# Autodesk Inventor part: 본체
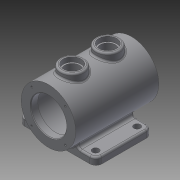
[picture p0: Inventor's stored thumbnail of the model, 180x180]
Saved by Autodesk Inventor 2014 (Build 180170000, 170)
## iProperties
Created: 2014-12
Part Number: 본체
Material: 일반
Document SubType Name: Modeling
Designer: Owner
Density: 1 g/cm^3
Appearance: 기본값
Author: Owner
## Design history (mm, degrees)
sketch "스케치1"
  geometry: C1 r 46 at (0, 0); 1 further point
  constraints: 1 centre point, 1 coincident
  dimensions: "d0" = 92 diameter of C1
extrude "돌출1" new body sketch "스케치1" stored distance "d1" = 140; taper "d2" = 0 deg
sketch "스케치2"
  geometry: C1 r 46 at (0, 0) reference; C2 r 30 at (0, 0)
  constraints: 1 centre point, 1 coincident
  dimensions: "d3" = 60 diameter of C2
extrude "돌출2" cut sketch "스케치2" stored distance "d4" = 0; taper "d5" = 0 deg
node "작업 평면1"
sketch "스케치3" dims "d28" = 40
  geometry: C1 r 37.5 at (0, 0); 1 further point
  constraints: 1 centre point, 1 coincident
  dimensions: "d7" = 75 diameter of C1
extrude "돌출3" cut sketch "스케치3" distance "d8" = 116; taper "d9" = 0 deg
node "작업 평면2"
sketch "스케치5"
  geometry: L1 (65, 40)-(-65, 40); L2 (-65, 40)-(-65, -55); L3 (-65, -55)-(65, -55); L4 (65, -55)-(65, 40); L5 (-46, -70)-(46, -70) reference; L6 (46, 70)-(-46, 70) reference; 2 further points
  constraints: 8 end point, 2 parallel, 1 horizontal, 1 midpoint, 1 perpendicular, 1 vertical alignment
  dimensions: "d13" = 130 distance of L3.end L2.end; "d14" = 95 distance of L2.end L1.end; "d15" = 15 distance between parallel lines of L5 L3
extrude "돌출4" join sketch "스케치5" distance "d16" = 12; taper "d17" = 0 deg
node "작업 평면3"
sketch "스케치7"
  geometry: L1 (-130, 6)-(-90.923, 6) reference; L2 (-130, -6)-(-130, 6) reference; L3 (-130, -6)-(0, -6) reference; L4 (0, -6)-(0, 6) reference; L5 (-39.077, 6)-(0, 6) reference; L6 (-39.077, 6)-(0, 6) reference; L7 (-130, 6)-(-90.923, 6) reference; C1 r 30 at (-65, 44) reference; C2 r 46 at (-65, 44) reference; A1 r 46 centre (-65, 44) between (-90.923, 6) and (-39.077, 6) reference; A2 r 5 centre (-26.116, 11) between (-29.928, 14.235) and (-26.116, 6); A3 r 5 centre (-103.884, 11) between (-103.884, 6) and (-100.072, 14.235); A4 r 46 centre (-65, 44) between (-39.077, 6) and (-90.923, 6) reference; 1 further point
  constraints: 6 point on circle, 4 tangent, 2 centre point, 2 point on line
  dimensions: "d18" = 10 diameter of A2; "d19" = 10 diameter of A3
extrude "돌출5" join sketch "스케치7" distance "d20" = 95; taper "d21" = 0 deg
node "작업 평면5"
sketch "스케치9"
  geometry: L1 (46, 70)-(-46, 70) reference; C1 r 20 at (0, 30); C2 r 20 at (0, -30); 1 further point
  constraints: 2 centre point, 2 vertical alignment
  dimensions: "d27" = 40 diameter of C1; "d28" = 40 diameter of C2; "d29" = 40 distance from line of C1.centre L1; "d30" = 60 distance of C2.centre C1.centre
extrude "돌출6" join sketch "스케치9" stored distance "d31" = 95; taper "d32" = 0 deg
sketch "스케치10"
  geometry: C1 r 20 at (0, 0) reference; 1 further point
sketch "스케치11"
  geometry: C1 r 20 at (0, 0) reference; 1 further point
hole "구멍1" sketch "스케치10" diameter "d33" = 25; stored, may be unused: countersink angle "d37" = 90 deg, drill point angle "d39" = 118 deg; dims "d34" = 6, "d35" = 30, "d36" = 8, "d38" = 8
hole "구멍2" sketch "스케치11" diameter "d40" = 25; stored, may be unused: countersink angle "d44" = 90 deg, drill point angle "d46" = 118 deg; dims "d41" = 6, "d42" = 30, "d43" = 8, "d45" = 8
sketch "스케치12"
  geometry: L1 (-38.884, 40)-(-65, 40) reference; L2 (-65, 40)-(-65, -55) reference; L3 (-65, -55)-(-38.884, -55) reference; C1 r 5.5 at (-52, 27.5); C2 r 5.5 at (-52, -42.5); 2 further points
  constraints: 2 centre point, 1 other
  dimensions: "d47" = 11 diameter of C1; "d48" = 11 diameter of C2; "d49" = 12.5 distance from line of C1.centre L1; "d50" = 12.5 distance from line of C2.centre L3; "d51" = 13 distance from line of C2.centre L2; "d52" = 13 distance from line of C1.centre L2
extrude "돌출7" cut sketch "스케치12" stored distance "d53" = 95; taper "d54" = 0 deg
sketch "스케치13"
  geometry: L1 (-65, 40)-(-65, -55) reference; C1 r 5.5 at (-52, 27.5) reference; 2 further points
  constraints: 1 other
  dimensions: "d55" = 8 distance from line of point (-57, -7.5) L1; "d56" = 35 vertical distance of point (-57, -7.5) C1.centre
feature "엠보싱1" sketch "스케치13" dims "d57" = 1, "d58" = 0
sketch "스케치14"
  geometry: L1 (0, 0)-(28.284, 28.284); L2 (0, 0)-(40, 0); L3 (0, 0)-(-28.284, 28.284); L4 (0, 0)-(-28.284, -28.284); L5 (0, 0)-(28.284, -28.284); C1 r 30 at (0, 0) reference; C2 r 46 at (0, 0) reference
  constraints: 10 end point, 1 equal length, 1 horizontal, 13 other
  dimensions: "d59" = 40 distance of L1.start L1.end; "d60" = 45 deg angle of L2 L1; "d63" = 360 deg dimension on C1.centre L1.end (derived)
hole "구멍3" sketch "스케치14" at (28.284, 28.284), (-28.284, 28.284), (-28.284, -28.284), (28.284, -28.284) diameter "d65" = 3.242; stored, may be unused: countersink angle "d69" = 90 deg, drill point angle "d71" = 118 deg; dims "d66" = 8, "d67" = 30, "d68" = 8, "d70" = 10
fillet "모깎기1" dims "d72" = 10
fillet "모깎기2" dims "d73" = 3
fillet "모깎기3" dims "d74" = 3
fillet "모깎기4" dims "d75" = 3
chamfer "모따기1" distance "d76" = 1; stored, may be unused: second distance "d77" = 2, angle "d78" = 45 deg
node "솔리드1"
mirror "대칭1"
mirror "대칭2"
node "투영된 루프1"
node "투영된 루프2"
node "투영된 루프3"
other parameters: "d6" = 58, "d26" = 56
